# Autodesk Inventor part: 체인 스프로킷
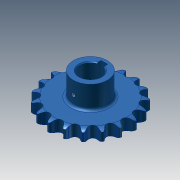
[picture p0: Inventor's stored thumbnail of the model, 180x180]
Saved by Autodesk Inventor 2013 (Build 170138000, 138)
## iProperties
Company: 한국ATC센터
CustomPartVersion: 1
Created: 2014-07
Part Number: 체인 스프로킷
Material: 강철
Document SubType Name: Modeling
Designer: KYOUNG IL JANG
Density: 7.85 g/cm^3
Mass: 738.6 g
Surface Area: 236.854 cm^2
Volume: 94.0892 cm^3
Author: KYOUNG IL JANG
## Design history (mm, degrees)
sketch "이론적 톱니 프로파일"
  geometry: L1 (0, 0)-(0, 45.567); L2 (0, 0)-(14.795, 43.098); L3 (0, 45.567)-(14.795, 43.098); L4 (0, 45.567)-(5.661, 50.015); L5 (5.661, 50.015)-(-5.141, 45.406); L6 (-12.428, 43.493)-(-5.573, 46.417); L7 (-5.141, 45.406)-(-5.573, 46.417); L8 (5.573, 46.417)-(5.141, 45.406); L9 (0, 0)-(8.138, 48.771); A1 r 45.567 centre (0, 0) between (0, 45.567) and (14.795, 43.098); A2 r 49.445 centre (0, 0) between (7.302, 48.903) and (-7.302, 48.903); A3 r 4.545 centre (0, 45.567) between (-3.574, 42.758) and (3.574, 42.758); A4 r 7.453 centre (12.428, 43.493) between (7.302, 48.903) and (5.573, 46.417); A5 r 7.453 centre (-12.428, 43.493) between (-5.573, 46.417) and (-7.302, 48.903); A6 r 11.745 centre (5.661, 50.015) between (-5.141, 45.406) and (-3.574, 42.758); A7 r 11.745 centre (-5.661, 50.015) between (3.574, 42.758) and (5.141, 45.406); 2 further points
  constraints: 18 end point, 15 point on circle, 7 centre point, 3 coincident, 3 point on line, 3 symmetric about line, 3 tangent, 1 equal radius, 1 midpoint, 1 parallel, 1 vertical, 1 other
  dimensions: "d0" = 91.13301 diameter of A1 (computed from da_p, da_z); "d2" = 18.9474 deg angle of L2 L1 (computed from da_z); "d3" = 4.545 radius of A3 (= 0.5 x da_Dr + da_SC); "d10" = 128.158 deg angle of L4 L1 (computed from da_z); "d11" = 15.0526 deg angle of L5 L4 (computed from da_z); "d12" = 7.2 distance of L3.start L4.end (= 0.8 x da_Dr); "d13" = 11.745 distance of L4.end L5.end (= 1.3 x da_Dr + da_SC); "d14" = 12.6 distance of A4.centre L1.end (= 1.4 x da_Dr); "d23" = 4.5 distance from line of L9.end L3 (= da_Ha)
sketch "톱니 프로파일"
  geometry: L1 (0, 0)-(0, 45.567); L2 (0, 45.567)-(4.203, 43.837); L3 (0, 45.567)-(-4.203, 43.837); A1 r 4.545 centre (0, 45.567) between (-4.203, 43.837) and (4.203, 43.837); A2 r 22.68 centre (25.176, 35.206) between (7.12, 48.93) and (4.203, 43.837); A3 r 22.68 centre (-25.176, 35.206) between (-4.203, 43.837) and (-7.12, 48.93); A4 r 49.445 centre (0, 0) between (-7.12, 48.93) and (7.12, 48.93) reference; 1 further point
  constraints: 9 point on circle, 6 end point, 3 centre point, 2 tangent, 1 coincident, 1 equal radius, 1 vertical, 1 other
  dimensions: "d44" = 135.263 deg angle of L3 L2 (= da_Alfa); "d45" = 22.68 radius of A2 (= da_Re); "d46" = 4.545 radius of A1 (= da_Ri)
sketch "단면 프로파일"
  geometry: L1 (49.445, 0)-(-49.445, 0) reference; L2 (33.265, 6.65)-(-33.265, 6.65); L3 (-33.265, 6.65)-(-33.265, -6.65); L4 (-33.265, -6.65)-(33.265, -6.65); L5 (33.265, -6.65)-(33.265, 6.65); L6 (33.265, 6.65)-(49.445, 6.65); L7 (49.445, 6.65)-(49.445, -6.65); L8 (49.445, -6.65)-(33.265, -6.65); L9 (33.265, -6.65)-(33.265, 6.65); L10 (42.183, 6.65)-(0, 6.65); L11 (0, 6.65)-(0, -6.65); L12 (0, -6.65)-(42.183, -6.65); L13 (0, 6.65)-(0, -6.65); L14 (49.445, 4.775)-(49.445, -4.775); A1 r 15 centre (42.183, -8.35) between (49.445, 4.775) and (42.183, 6.65); A2 r 15 centre (42.183, 8.35) between (42.183, -6.65) and (49.445, -4.775); 2 further points
  constraints: 26 end point, 7 midpoint, 5 perpendicular, 4 parallel, 4 point on circle, 3 point on line, 3 symmetric about line, 2 centre point, 2 horizontal, 2 tangent, 1 collinear, 1 other
  dimensions: "d30" = 13.3 distance between parallel lines of L8 L6 (= da_Bf); "d31" = 66.53007 distance between parallel lines of L3 L5 (= da_Ds); "d32" = 13.3 distance between parallel lines of L4 L2 (= da_Bs); "d33" = 1.875 distance from line of L14.start L6 (= da_Ba); "d34" = 15 radius of A1 (= da_Rx); "d43" = 6.65 distance between parallel lines of L4 L1 (computed from da_k, da_pt, da_Bs)
revolve "슈라우드" stored, may be unused: angle "d36" = 90 deg
revolve "스트랜드" stored, may be unused: angle "d37" = 90 deg
extrude "이론적 톱니" cut sketch "이론적 톱니 프로파일" stored distance "d18" = 10; taper "d19" = 0 deg; dims "d49" = 0, "form_type" = 0 [user parameter]
extrude "톱니" cut sketch "톱니 프로파일" stored distance "d47" = 10; taper "d48" = 0 deg; dims "d50" = 10, "form_type" = 0 [user parameter]
node "타이밍 평면"
node "작업 평면3"
sketch "스케치5"
  geometry: C1 r 20 at (0, -45.567); 1 further point
  constraints: 1 centre point, 1 coincident
  dimensions: "d52" = 40 diameter of C1
extrude "돌출4" join sketch "스케치5" stored distance "d53" = 10; taper "d54" = 0 deg
sketch "스케치6"
  geometry: L1 (4, 11.843)-(4, 16.5); L2 (4, 16.5)-(-4, 16.5); L3 (-4, 16.5)-(-4, 11.843); A1 r 12.5 centre (0, 0) between (4, 11.843) and (-4, 11.843); 1 further point
  constraints: 6 end point, 2 parallel, 2 point on circle, 1 centre point, 1 coincident, 1 perpendicular, 1 vertical
  dimensions: "d55" = 25 diameter of A1; "d56" = 29 dimension on A1 L2 (computed from d55); "d57" = 8 distance of L1.end L2.end
extrude "돌출5" cut sketch "스케치6" stored distance "d58" = 10; taper "d59" = 0 deg
fillet "모깎기2" dims "d60" = 3
chamfer "모따기1" distance "d61" = 1; stored, may be unused: second distance "d62" = 2, angle "d63" = 45 deg
node "작업 평면4"
sketch "스케치7"
  geometry: L1 (-13.5, -13.3)-(13.5, -13.3) reference; 4 further points
  constraints: 1 vertical alignment
  dimensions: "d65" = 25 distance from line of point (0, 11.7) L1
hole "구멍1" sketch "스케치7" at (0, 11.7) diameter "d66" = 4.134; stored, may be unused: countersink angle "d70" = 90 deg, drill point angle "d72" = 118 deg; dims "d67" = 6, "d68" = 4, "d69" = 2, "d71" = 8
body "Solid1"
pattern_linear "스트랜드 패턴" dims "d40" = 24 (= da_pt)
pattern_circular "톱니 패턴" dims angle "d21" = 360 deg
other parameters: "da_p" = 15 [user parameter; used in 1 equation term], "da_Dr" = 9 [user parameter; used in 4 equation terms], "da_SC" = 0.045 [user parameter; used in 2 equation terms], "da_Ha" = 4.5 [user parameter; used in 1 equation term], "da_pt" = 24 [user parameter; used in 2 equation terms], "da_Bf" = 13.3 [user parameter; used in 1 equation term], "d28" = 0, "d29" = 0, "da_Ba" = 1.875 [user parameter; used in 1 equation term], "da_Rx" = 15 [user parameter; used in 1 equation term], "da_Ra" = 0.6 [user parameter], "da_Bs" = 13.3 [user parameter; used in 2 equation terms], "da_Ds" = 66.53007 [user parameter; used in 1 equation term], "d42" = 0, "da_Re" = 22.68 [user parameter; used in 1 equation term], "da_Ri" = 4.545 [user parameter; used in 1 equation term], "da_Alfa" = 135.263 deg [user parameter; used in 1 equation term]
